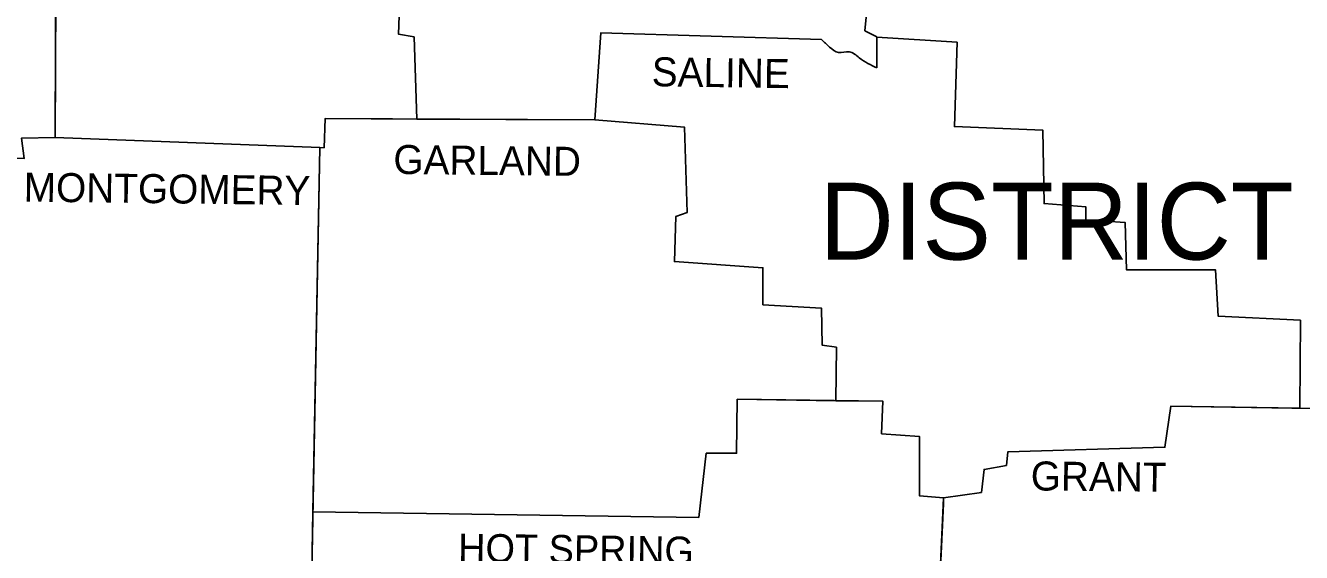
# Model space of a CAD drawing. Extents: x 1368042 to 1371376, y 380392 to 382637.
# Drawn here: x 1369334.7 to 1369729.7, y 381061.8 to 381224.9 of the extents above; entities that cross this region are included whole.
import ezdxf

# ---------------------------------------------------------------- set-up
doc = ezdxf.new("R2010")
doc.units = 0
doc.layers.add('Default', color=7, linetype='Continuous')
doc.layers.add('R_No Plot', color=7, linetype='Continuous')

msp = doc.modelspace()

# ---------------------------------------------------------------- linework, layer by layer
at = {"layer": 'Default'}
for p, q in [((1369598.25, 381221.24), (1369598.25, 381211.75)), ((1369598.25, 381221.24), (1369623.1, 381219.68)), ((1369623.1, 381219.68), (1369622.27, 381193.58)), ((1369425.76, 381187.11), (1369423.33, 381055.97)), ((1369650.04, 381169.78), (1369662.99, 381168.73)), ((1369662.99, 381168.73), (1369662.99, 381164.76)), ((1369662.99, 381164.76), (1369675.1, 381163.93)), ((1369675.1, 381163.93), (1369675.52, 381149.31)), ((1369581.34, 381125.92), (1369585.72, 381125.3)), ((1369585.72, 381125.3), (1369585.5, 381108.79)), ((1369729.18, 381106.46), (1369739.21, 381106.29))]:
    msp.add_line(p, q, dxfattribs=at)
for points in [[(1369344.2, 381275.78), (1369343.9, 381190.24), (1369333.46, 381190.03), (1369334.3, 381183.77), (1369324.27, 381183.97), (1369324.07, 381179.38), (1369314.25, 381179.38), (1369314.46, 381176.04), (1369299.84, 381175.62), (1369299.63, 381162.88), (1369285.43, 381164.14), (1369283.14, 381061.4), (1369202.74, 381061.61), (1369200.86, 381037.8), (1369203.78, 381035.71), (1369203.57, 381008.98), (1369143.36, 381011.63)], [(1369664.24, 381252.47), (1369649.67, 381254.09), (1369649.2, 381254.14), (1369649.83, 381248.5), (1369622.48, 381247.46), (1369621.64, 381239.31), (1369595.95, 381237.85), (1369594.49, 381223.23), (1369598.25, 381221.35), (1369598.25, 381221.24)], [(1369664.24, 381252.47), (1369649.2, 381254.14), (1369649.83, 381248.5), (1369622.48, 381247.46), (1369621.64, 381239.31), (1369595.95, 381237.85), (1369594.49, 381223.23), (1369598.25, 381221.35), (1369598.25, 381211.75)], [(1369450.4, 381227.83), (1369450.2, 381222.19), (1369455, 381221.35), (1369455.87, 381195.94)], [(1369581.13, 381220.52), (1369512.84, 381222.61), (1369510.96, 381195.67), (1369427.43, 381196.09), (1369427.1, 381187.06)], [(1369581.13, 381220.52), (1369512.84, 381222.61), (1369510.96, 381195.67)], [(1369729.18, 381106.46), (1369729.39, 381133.65), (1369703.92, 381134.9), (1369703.08, 381149.31), (1369675.52, 381149.31), (1369675.1, 381163.93), (1369662.99, 381164.76), (1369662.99, 381168.73), (1369650.04, 381169.78), (1369649.62, 381192.54), (1369622.27, 381193.58), (1369623.1, 381219.68), (1369598.25, 381221.24)], [(1369598.25, 381221.24), (1369623.1, 381219.68), (1369622.27, 381193.58), (1369649.62, 381192.54), (1369650.04, 381169.78), (1369662.99, 381168.73), (1369662.99, 381164.76), (1369675.1, 381163.93), (1369675.52, 381149.31), (1369703.08, 381149.31), (1369703.92, 381134.9), (1369729.39, 381133.65), (1369729.18, 381106.46)], [(1369510.96, 381195.67), (1369538.74, 381193.37), (1369539.57, 381167.06)], [(1369510.96, 381195.67), (1369538.74, 381193.37), (1369539.57, 381167.06), (1369536.02, 381165.81), (1369535.6, 381151.82), (1369562.96, 381149.94), (1369562.96, 381138.45), (1369581.13, 381137.41), (1369581.34, 381125.92), (1369585.72, 381125.3), (1369585.5, 381108.79)], [(1369425.76, 381187.11), (1369343.9, 381190.24)], [(1369622.27, 381193.58), (1369649.62, 381192.54), (1369650.04, 381169.78)], [(1369427.1, 381187.06), (1369425.76, 381187.11)], [(1369539.57, 381167.06), (1369536.02, 381165.81), (1369535.6, 381151.82), (1369562.96, 381149.94)], [(1369562.96, 381149.94), (1369562.96, 381138.45), (1369581.13, 381137.41), (1369581.34, 381125.92)], [(1369675.52, 381149.31), (1369703.08, 381149.31), (1369703.92, 381134.9)], [(1369703.92, 381134.9), (1369729.39, 381133.65), (1369729.18, 381106.46)], [(1369423.67, 381074.35), (1369543.12, 381072.67), (1369545.42, 381092.51), (1369554.82, 381092.51), (1369555.03, 381109.22), (1369600.13, 381108.59), (1369599.71, 381098.57), (1369611.41, 381097.73), (1369611.41, 381079.36), (1369618.93, 381078.73), (1369618.84, 381076.82)], [(1369585.5, 381108.79), (1369600.13, 381108.59), (1369599.71, 381098.57), (1369611.41, 381097.73), (1369611.41, 381079.36), (1369618.93, 381078.73)], [(1369739.21, 381106.29), (1369729.18, 381106.46), (1369689.3, 381107.13), (1369687.42, 381094.39), (1369638.76, 381092.93), (1369638.35, 381088.75), (1369631.45, 381087.5), (1369630.62, 381080.4), (1369618.93, 381078.73)], [(1369618.93, 381078.73), (1369630.62, 381080.4), (1369631.45, 381087.5), (1369638.35, 381088.75), (1369638.76, 381092.93), (1369687.42, 381094.39), (1369689.3, 381107.13), (1369729.18, 381106.46)], [(1369618.93, 381078.73), (1369630.62, 381080.4), (1369631.45, 381087.5), (1369638.35, 381088.75), (1369638.76, 381092.93), (1369687.42, 381094.39), (1369689.3, 381107.13), (1369739.21, 381106.29)], [(1369618.93, 381078.73), (1369618.84, 381076.82), (1369616.42, 381024.02), (1369614.54, 381024.65), (1369614.75, 380996.49)], [(1369618.93, 381078.73), (1369616.42, 381024.02), (1369614.54, 381024.65), (1369614.75, 380996.49)]]:
    msp.add_lwpolyline(points, dxfattribs=at)
msp.add_spline([(1369598.25, 381211.75), (1369592.82, 381214.88), (1369589.69, 381216.76), (1369586.35, 381216.55), (1369583.63, 381218.22), (1369581.13, 381220.52)], degree=3, dxfattribs=at)
msp.add_spline([(1369598.25, 381211.75), (1369592.82, 381214.88), (1369589.69, 381216.76), (1369586.35, 381216.55), (1369583.63, 381218.22), (1369581.13, 381220.52)], degree=3, dxfattribs=at)
at = {"layer": 'R_No Plot'}
for p, q in [((1369344.2, 381275.78), (1369343.9, 381190.24)), ((1369427.43, 381196.09), (1369427.1, 381187.06)), ((1369343.9, 381190.24), (1369425.76, 381187.11)), ((1369425.76, 381187.11), (1369343.9, 381190.24)), ((1369425.76, 381187.11), (1369423.67, 381074.35)), ((1369425.76, 381187.11), (1369427.1, 381187.06)), ((1369427.1, 381187.06), (1369425.76, 381187.11)), ((1369423.67, 381074.35), (1369423.33, 381055.97))]:
    msp.add_line(p, q, dxfattribs=at)
for points in [[(1369285.43, 381164.14), (1369299.63, 381162.88), (1369299.84, 381175.62), (1369314.46, 381176.04), (1369314.25, 381179.38), (1369324.07, 381179.38), (1369324.27, 381183.97), (1369334.3, 381183.77), (1369333.46, 381190.03), (1369343.9, 381190.24), (1369344.2, 381275.78)], [(1369598.25, 381211.75), (1369598.25, 381221.35), (1369594.49, 381223.23), (1369595.95, 381237.85), (1369621.64, 381239.31), (1369622.48, 381247.46), (1369649.83, 381248.5), (1369649.2, 381254.14), (1369649.67, 381254.09)], [(1369463.35, 381238.48), (1369458.97, 381237.22), (1369457.92, 381231.59), (1369454.58, 381231.79), (1369453.54, 381228.87), (1369450.4, 381227.83), (1369450.2, 381222.19)], [(1369455.87, 381195.94), (1369455, 381221.35), (1369450.2, 381222.19), (1369450.4, 381227.83)], [(1369450.2, 381222.19), (1369455, 381221.35), (1369455.87, 381195.94)], [(1369455.87, 381195.94), (1369510.96, 381195.67), (1369512.84, 381222.61), (1369581.13, 381220.52)], [(1369427.1, 381187.06), (1369427.43, 381196.09), (1369455.87, 381195.94)], [(1369510.96, 381195.67), (1369455.87, 381195.94), (1369427.43, 381196.09)], [(1369585.5, 381108.79), (1369585.72, 381125.3), (1369581.34, 381125.92), (1369581.13, 381137.41), (1369562.96, 381138.45), (1369562.96, 381149.94), (1369535.6, 381151.82), (1369536.02, 381165.81), (1369539.57, 381167.06), (1369538.74, 381193.37), (1369510.96, 381195.67)], [(1369343.9, 381190.24), (1369333.46, 381190.03), (1369334.3, 381183.77)], [(1369423.33, 381055.97), (1369423.67, 381074.35), (1369425.76, 381187.11)], [(1369618.93, 381078.73), (1369611.41, 381079.36), (1369611.41, 381097.73), (1369599.71, 381098.57), (1369600.13, 381108.59), (1369555.03, 381109.22), (1369554.82, 381092.51), (1369545.42, 381092.51), (1369543.12, 381072.67), (1369423.67, 381074.35)], [(1369423.67, 381074.35), (1369543.12, 381072.67), (1369545.42, 381092.51), (1369554.82, 381092.51), (1369555.03, 381109.22), (1369585.5, 381108.79)], [(1369614.54, 381024.65), (1369616.42, 381024.02), (1369618.84, 381076.82), (1369618.93, 381078.73)], [(1369423.67, 381074.35), (1369423.67, 381074.35)]]:
    msp.add_lwpolyline(points, dxfattribs=at)
msp.add_spline([(1369581.13, 381220.52), (1369583.63, 381218.22), (1369586.35, 381216.55), (1369589.69, 381216.76), (1369592.82, 381214.88), (1369598.25, 381211.75)], degree=3, dxfattribs=at)

# ---------------------------------------------------------------- texts
at = {"layer": 'Default'}
for s, height, rotation, p in [('SALINE', 8.981, 359.1492, (1369528.5, 381206.11)), ('GARLAND', 8.981, 359.3658, (1369448.53, 381178.96)), ('MONTGOMERY', 8.981, 359.2944, (1369334.09, 381170.4)), ('GRANT', 8.981, 359.4032, (1369645.86, 381081.03)), ('HOT SPRING', 8.772, 359.2216, (1369468.57, 381058.89))]:
    msp.add_text(s, height=height, rotation=rotation, dxfattribs=at).set_placement(p)
msp.add_text('DISTRICT 6', height=23.805, dxfattribs=at).set_placement((1369580.5, 381152.44))

doc.saveas('drawing.dxf')
